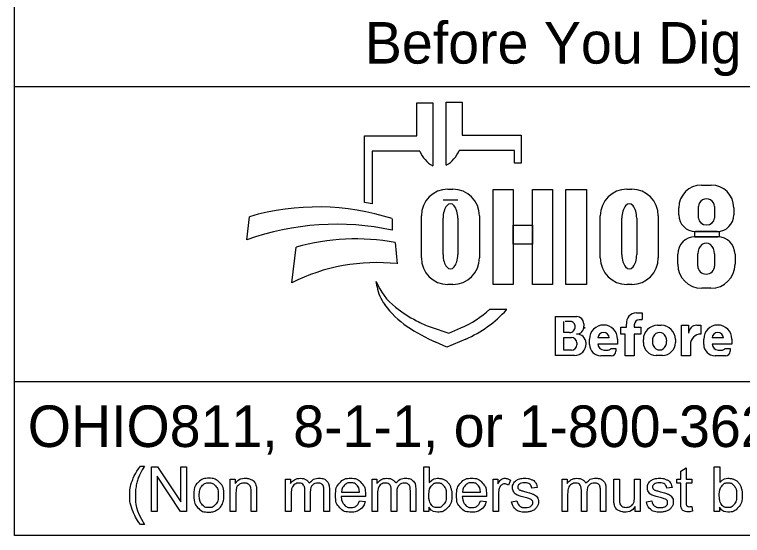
# Model space of a CAD drawing. Extents: x 0 to 34, y 0 to 22.
# Drawn here: x 2.978 to 5.431, y 2.143 to 3.897 of the extents above; entities that cross this region are included whole.
import ezdxf

# ---------------------------------------------------------------- set-up
doc = ezdxf.new("R2010")
doc.units = 0
doc.layers.add('SH_Data', color=7, linetype='Continuous')
doc.layers.add('SH_Text', color=7, linetype='Continuous')

msp = doc.modelspace()

# ---------------------------------------------------------------- linework, layer by layer
at = {"layer": 'SH_Data'}
for p, q in [((2.9775, 2.1428), (2.9775, 4.4803)), ((2.9775, 3.6553), (7.2275, 3.6553)), ((7.2275, 2.6607), (2.9775, 2.6607)), ((7.2275, 2.1428), (2.9775, 2.1428))]:
    msp.add_line(p, q, dxfattribs=at)
at = {"layer": 'SH_Text'}
for p, q in [((4.3335, 3.4883), (4.3335, 3.5998)), ((4.3335, 3.5998), (4.3872, 3.5998)), ((4.3872, 3.5998), (4.3872, 3.3877)), ((4.4329, 3.39), (4.4329, 3.6021)), ((4.4329, 3.6021), (4.4865, 3.6021)), ((4.4865, 3.6021), (4.4865, 3.4906)), ((4.1576, 3.2644), (4.1576, 3.4883)), ((4.1576, 3.4883), (4.3335, 3.4883)), ((4.4865, 3.4906), (4.6857, 3.4906)), ((4.6857, 3.4906), (4.6857, 3.3968)), ((4.1828, 3.4369), (4.1828, 3.26)), ((4.3439, 3.4369), (4.1828, 3.4369)), ((4.6625, 3.4392), (4.4761, 3.4392)), ((4.6625, 3.3968), (4.6625, 3.4392)), ((4.6857, 3.3968), (4.6625, 3.3968)), ((5.2931, 3.3231), (5.3258, 3.3231)), ((4.4385, 3.3091), (4.4551, 3.3091)), ((5.0416, 3.3091), (5.0581, 3.3091)), ((4.4718, 3.2721), (4.422, 3.2721)), ((5.2168, 3.2225), (5.2168, 3.2468)), ((5.283, 3.2111), (5.283, 3.2504)), ((5.3371, 3.2504), (5.3371, 3.2111)), ((5.4022, 3.2468), (5.4022, 3.2225)), ((3.7602, 3.1381), (3.7696, 3.2162)), ((4.3491, 3.0776), (4.3491, 3.2196)), ((4.5445, 3.2196), (4.5445, 3.0776)), ((4.9521, 3.0776), (4.9521, 3.2196)), ((5.1476, 3.2196), (5.1476, 3.0776)), ((4.2509, 3.2097), (4.2509, 3.1709)), ((4.422, 3.089), (4.422, 3.2114)), ((4.4718, 3.2114), (4.4718, 3.089)), ((5.025, 3.089), (5.025, 3.2114)), ((5.0748, 3.2114), (5.0748, 3.089)), ((5.3462, 3.1665), (5.2728, 3.1665)), ((5.271, 3.1482), (5.3483, 3.1482)), ((4.2608, 3.1291), (4.2671, 3.0582)), ((3.912, 2.9936), (3.9267, 3.1137)), ((5.2131, 3.0563), (5.2131, 3.0903)), ((5.2806, 3.0503), (5.2806, 3.0912)), ((5.3374, 3.0912), (5.3374, 3.0503)), ((5.4062, 3.0903), (5.4062, 3.0563)), ((4.1997, 2.9807), (4.1967, 2.9986)), ((4.4551, 2.9882), (4.4385, 2.9882)), ((5.0581, 2.9882), (5.0416, 2.9882)), ((5.3252, 2.9753), (5.2941, 2.9753)), ((4.58, 2.9048), (4.6375, 2.9048)), ((4.8013, 2.749), (4.8013, 2.8798)), ((4.8013, 2.8798), (4.8725, 2.8798)), ((5.0739, 2.8926), (5.0934, 2.8926)), ((5.0934, 2.8926), (5.0934, 2.8696)), ((4.8293, 2.8263), (4.8293, 2.8632)), ((4.8545, 2.8632), (4.8332, 2.8632)), ((4.8963, 2.856), (4.8963, 2.8481)), ((5.0406, 2.8442), (5.0406, 2.8546)), ((5.0667, 2.8526), (5.0667, 2.8442)), ((5.0934, 2.8691), (5.0832, 2.8691)), ((5.1451, 2.8508), (5.1573, 2.8508)), ((5.2254, 2.7478), (5.2254, 2.8505)), ((5.2254, 2.8505), (5.2499, 2.8505)), ((5.2499, 2.8505), (5.2499, 2.8237)), ((5.2772, 2.8505), (5.291, 2.8505)), ((5.291, 2.8505), (5.291, 2.8209)), ((4.3816, 2.8444), (4.441, 2.8239)), ((4.441, 2.8239), (4.4821, 2.8417)), ((4.8487, 2.8263), (4.8293, 2.8263)), ((5.0213, 2.8212), (5.0213, 2.8442)), ((5.0213, 2.8442), (5.0406, 2.8442)), ((5.0667, 2.8442), (5.0883, 2.8442)), ((5.0883, 2.8442), (5.0883, 2.8212)), ((4.4983, 2.8044), (4.435, 2.7769)), ((4.8293, 2.7669), (4.8293, 2.8097)), ((4.8293, 2.8097), (4.8548, 2.8097)), ((4.9159, 2.7858), (4.9159, 2.8042)), ((4.9824, 2.8082), (4.9439, 2.8082)), ((5.0104, 2.8042), (5.0104, 2.7866)), ((5.0362, 2.8212), (5.0213, 2.8212)), ((5.0362, 2.7478), (5.0362, 2.8212)), ((5.0883, 2.8212), (5.0667, 2.8212)), ((5.0667, 2.8212), (5.0667, 2.7478)), ((5.0973, 2.7922), (5.0973, 2.8029)), ((5.2051, 2.8029), (5.2051, 2.7922)), ((5.3008, 2.7858), (5.3008, 2.8042)), ((5.3674, 2.8082), (5.3288, 2.8082)), ((5.3953, 2.8042), (5.3953, 2.7866)), ((4.435, 2.7769), (4.3976, 2.7934)), ((4.8729, 2.7916), (4.8729, 2.7853)), ((4.9043, 2.7887), (4.9043, 2.7884)), ((5.0104, 2.7866), (4.944, 2.7866)), ((4.9876, 2.7729), (5.0045, 2.7729)), ((5.0045, 2.7729), (5.0045, 2.7631)), ((5.2559, 2.786), (5.2559, 2.7478)), ((5.3953, 2.7866), (5.3289, 2.7866)), ((5.3725, 2.7729), (5.3894, 2.7729)), ((5.3894, 2.7729), (5.3894, 2.7631)), ((4.865, 2.749), (4.8013, 2.749)), ((4.8546, 2.7669), (4.8293, 2.7669)), ((4.9649, 2.7673), (4.979, 2.7673)), ((5.1623, 2.7494), (5.1401, 2.7494)), ((5.3498, 2.7673), (5.3639, 2.7673)), ((4.9892, 2.7478), (4.9538, 2.7478)), ((5.0667, 2.7478), (5.0362, 2.7478)), ((5.2559, 2.7478), (5.2254, 2.7478)), ((5.3742, 2.7478), (5.3388, 2.7478))]:
    msp.add_line(p, q, dxfattribs=at)
for points in [[(4.591, 3.3081), (4.6589, 3.3081), (4.6589, 2.9881), (4.591, 2.9881)], [(4.7231, 3.3081), (4.7911, 3.3081), (4.7911, 2.9881), (4.7231, 2.9881)], [(4.8364, 3.3081), (4.9052, 3.3081), (4.9052, 2.9881), (4.8364, 2.9881)], [(4.6589, 3.1882), (4.7231, 3.1882), (4.7231, 3.1242), (4.6589, 3.1242)], [(5.2706, 3.1665), (5.3523, 3.1665), (5.3523, 3.1481), (5.2706, 3.1481)]]:
    msp.add_lwpolyline(points, close=True, dxfattribs=at)
for points in [[(3.4021, 2.3766), (3.4153, 2.3766)], [(3.4389, 2.2239), (3.4389, 2.3741), (3.4592, 2.3741), (3.5382, 2.2561), (3.5382, 2.3741), (3.5572, 2.3741), (3.5572, 2.2239), (3.5369, 2.2239), (3.4579, 2.3419), (3.4579, 2.2239), (3.4389, 2.2239)], [(4.3743, 2.2239), (4.3573, 2.2239), (4.3573, 2.3741), (4.3757, 2.3741), (4.3757, 2.3206)], [(5.2233, 2.2558), (5.2233, 2.3185), (5.2097, 2.3185), (5.2097, 2.3328), (5.2233, 2.3328), (5.2233, 2.3597), (5.2417, 2.3708), (5.2417, 2.3328), (5.2601, 2.3328), (5.2601, 2.3185), (5.2417, 2.3185), (5.2417, 2.2547)], [(5.3534, 2.2239), (5.3363, 2.2239), (5.3363, 2.3741), (5.3548, 2.3741), (5.3548, 2.3206)], [(3.7048, 2.2239), (3.7048, 2.3328), (3.7214, 2.3328), (3.7214, 2.3173)], [(3.8912, 2.2239), (3.8912, 2.3328), (3.9077, 2.3328), (3.9077, 2.3174)], [(4.1826, 2.2239), (4.1826, 2.3328), (4.1991, 2.3328), (4.1991, 2.3174)], [(4.5904, 2.2239), (4.5904, 2.3328), (4.607, 2.3328), (4.607, 2.3163)], [(4.8236, 2.2239), (4.8236, 2.3328), (4.8401, 2.3328), (4.8401, 2.3174)], [(4.9979, 2.2654), (4.9979, 2.3328), (5.0164, 2.3328), (5.0164, 2.2724)], [(5.0676, 2.2745), (5.0676, 2.3328), (5.0861, 2.3328), (5.0861, 2.2239), (5.0696, 2.2239)], [(4.6495, 2.3293), (4.643, 2.3122)], [(3.7233, 2.2833), (3.7233, 2.2239), (3.7048, 2.2239)], [(3.7932, 2.2908), (3.7932, 2.2239), (3.7748, 2.2239), (3.7748, 2.2901)], [(3.9743, 2.2871), (3.9743, 2.2239), (3.9559, 2.2239), (3.9559, 2.2946)], [(4.0388, 2.2986), (4.0388, 2.2239), (4.0203, 2.2239), (4.0203, 2.2924)], [(4.0799, 2.2887), (4.1406, 2.2887)], [(4.2657, 2.2871), (4.2657, 2.2239), (4.2473, 2.2239), (4.2473, 2.2946)], [(4.3301, 2.2986), (4.3301, 2.2239), (4.3117, 2.2239), (4.3117, 2.2924)], [(4.4879, 2.2887), (4.5486, 2.2887)], [(4.7394, 2.3046), (4.7213, 2.3022)], [(4.9067, 2.2871), (4.9067, 2.2239), (4.8883, 2.2239), (4.8883, 2.2946)], [(4.9711, 2.2986), (4.9711, 2.2239), (4.9527, 2.2239), (4.9527, 2.2924)], [(5.194, 2.3046), (5.1759, 2.3022)], [(3.9097, 2.2803), (3.9097, 2.2239), (3.8912, 2.2239)], [(4.16, 2.2736), (4.0788, 2.2736)], [(4.1404, 2.2591), (4.1595, 2.2567)], [(4.201, 2.2803), (4.201, 2.2239), (4.1826, 2.2239)], [(4.568, 2.2736), (4.4868, 2.2736)], [(4.5484, 2.2591), (4.5675, 2.2567)], [(4.6088, 2.2809), (4.6088, 2.2239), (4.5904, 2.2239)], [(4.653, 2.2564), (4.6712, 2.2593)], [(4.842, 2.2803), (4.842, 2.2239), (4.8236, 2.2239)], [(5.1076, 2.2564), (5.1258, 2.2593)], [(4.3743, 2.2375), (4.3743, 2.2239)], [(5.0696, 2.2239), (5.0696, 2.24)], [(5.2601, 2.2404), (5.2628, 2.2241)], [(5.3534, 2.2375), (5.3534, 2.2239)], [(3.4153, 2.1798), (3.4021, 2.1798)]]:
    msp.add_lwpolyline(points, dxfattribs=at)
for centre, radius, start, end in [((4.4353, 3.4736), 0.0985, 201.9296, 240.7469), ((4.3847, 3.476), 0.0985, 299.2531, 338.0704), ((5.2931, 3.2468), 0.0763, 90, 180), ((5.3258, 3.2468), 0.0763, 0, 90), ((4.4385, 3.2196), 0.0895, 90, 180), ((4.4551, 3.2196), 0.0895, 0, 90), ((5.0416, 3.2196), 0.0895, 90, 180), ((5.0581, 3.2196), 0.0895, 0, 90), ((4.0295, 2.4554), 0.8191, 79.2074, 81.0007), ((3.9997, 2.4302), 0.8191, 72.1402, 106.3144), ((5.2728, 3.2225), 0.056, 180, 270), ((5.3462, 3.2225), 0.056, 270, 0), ((4.0628, 2.2991), 0.8919, 77.8238, 109.8274), ((4.1267, 2.4094), 0.7322, 79.44, 105.8467), ((5.271, 3.0903), 0.0579, 90, 180), ((5.3483, 3.0903), 0.0579, 0, 90), ((4.4385, 3.0776), 0.0895, 180, 270), ((4.4551, 3.0776), 0.0895, 270, 0), ((5.0416, 3.0776), 0.0895, 180, 270), ((5.0581, 3.0776), 0.0895, 270, 0), ((4.1987, 2.4262), 0.6357, 83.8248, 116.8021), ((5.2941, 3.0563), 0.081, 180, 270), ((5.3252, 3.0563), 0.081, 270, 0), ((4.3841, 3.0707), 0.2008, 201.0457, 232.5314), ((4.341, 3.0048), 0.1433, 189.6817, 216.0884), ((4.4747, 3.1022), 0.3088, 216.0884, 235.7167), ((4.5766, 3.3219), 0.5173, 232.5314, 241.794), ((4.3387, 3.1722), 0.3602, 293.4582, 312.0712), ((4.3387, 3.1722), 0.401, 293.4582, 317.8286), ((4.8725, 2.856), 0.0238, 0, 90), ((5.0739, 2.859), 0.0335, 90, 187.5187), ((4.6412, 3.3465), 0.6044, 235.7167, 246.2325), ((4.4914, 3.1631), 0.3371, 241.794, 250.9821), ((4.8505, 2.8463), 0.0169, 357.8325, 90), ((4.8721, 2.8453), 0.0243, 270, 6.6529), ((4.9631, 2.8042), 0.0473, 0, 180), ((5.0832, 2.8526), 0.0165, 90, 180), ((5.1451, 2.8029), 0.0478, 90, 180), ((5.1573, 2.8029), 0.0478, 0, 90), ((5.2768, 2.8237), 0.0269, 89.2449, 180), ((5.3481, 2.8042), 0.0473, 0, 180), ((4.8487, 2.845), 0.0187, 270, 2.0582), ((4.8827, 2.8438), 0.0175, 347.4023, 0), ((4.9632, 2.8072), 0.0193, 2.9632, 177.0368), ((5.3481, 2.8072), 0.0193, 2.9632, 177.0368), ((4.8548, 2.7916), 0.0181, 0, 90), ((4.8722, 2.7889), 0.0321, 4.0748, 90), ((5.2908, 2.786), 0.0349, 89.6033, 180), ((4.8546, 2.7853), 0.0184, 270, 0), ((4.865, 2.7884), 0.0393, 270, 0), ((4.8714, 2.7887), 0.033, 0, 11.7502), ((4.9538, 2.7858), 0.038, 180, 270), ((4.9649, 2.7883), 0.021, 184.827, 270), ((4.979, 2.7767), 0.00938, 270, 335.9979), ((5.1401, 2.7922), 0.0428, 180, 270), ((5.1623, 2.7922), 0.0428, 270, 0), ((5.3388, 2.7858), 0.038, 180, 270), ((5.3498, 2.7883), 0.021, 184.827, 270), ((5.3639, 2.7767), 0.00938, 270, 335.9979), ((4.9892, 2.7631), 0.0152, 270, 0), ((5.3742, 2.7631), 0.0152, 270, 0)]:
    msp.add_arc(centre, radius, start, end, dxfattribs=at)
for centre, major_axis, ratio, start_param, end_param in [((5.31, 3.2504), (0.0271, 0), 0.969373, 0, 3.141593), ((4.4469, 3.2114), (0, 0.0484), 0.514403, 4.712389, 7.853982), ((5.0499, 3.2114), (0, 0.0484), 0.514403, 4.712389, 7.853982), ((5.31, 3.2111), (0.0271, 0), 0.818453, 3.141593, 6.283185), ((5.309, 3.0912), (0, 0.0358), 0.794529, 4.712389, 7.853982), ((4.4469, 3.089), (0, 0.0484), 0.514403, 1.570796, 4.712389), ((5.0499, 3.089), (0, 0.0484), 0.514403, 1.570796, 4.712389), ((5.309, 3.0503), (0.0284, 0), 0.959837, 3.141593, 6.283185), ((5.1517, 2.7976), (0, 0.029), 0.832186, 4.712389, 7.853982), ((5.1517, 2.7976), (0, 0.0302), 0.797287, 1.570796, 4.712389)]:
    msp.add_ellipse(centre, major_axis=major_axis, ratio=ratio, start_param=start_param, end_param=end_param, dxfattribs=at)
for points in [[(3.4021, 2.1798), (3.3869, 2.199), (3.3763, 2.2248), (3.3657, 2.2506), (3.3657, 2.2783), (3.3657, 2.3026), (3.3736, 2.325), (3.3829, 2.3509), (3.4021, 2.3766)], [(3.4153, 2.3766), (3.4029, 2.3553), (3.3989, 2.3462), (3.3927, 2.332), (3.3891, 2.3167), (3.3847, 2.2975), (3.3847, 2.2782), (3.3847, 2.2289), (3.4153, 2.1798)], [(3.5814, 2.2783), (3.5814, 2.3085), (3.5981, 2.3231), (3.6122, 2.3352), (3.6323, 2.3352), (3.6547, 2.3352), (3.669, 2.3205), (3.6832, 2.3058), (3.6832, 2.2799), (3.6832, 2.2589), (3.6769, 2.2469), (3.6706, 2.2348), (3.6586, 2.2282), (3.6466, 2.2215), (3.6323, 2.2215), (3.6095, 2.2215), (3.5954, 2.2362), (3.5814, 2.2508), (3.5814, 2.2783)], [(3.7214, 2.3173), (3.7334, 2.3352), (3.756, 2.3352), (3.7659, 2.3352), (3.7741, 2.3316), (3.7823, 2.3281), (3.7864, 2.3224), (3.7905, 2.3166), (3.7922, 2.3087), (3.7932, 2.3036), (3.7932, 2.2908)], [(3.9077, 2.3174), (3.9128, 2.3254), (3.9214, 2.3303), (3.9299, 2.3352), (3.9407, 2.3352), (3.9528, 2.3352), (3.9606, 2.3301), (3.9683, 2.3251), (3.9715, 2.3161), (3.9844, 2.3352), (4.0051, 2.3352), (4.0213, 2.3352), (4.03, 2.3262), (4.0388, 2.3172), (4.0388, 2.2986)], [(4.1595, 2.2567), (4.155, 2.24), (4.1428, 2.2307), (4.1306, 2.2215), (4.1117, 2.2215), (4.0878, 2.2215), (4.0738, 2.2362), (4.0598, 2.2509), (4.0598, 2.2774), (4.0598, 2.3049), (4.074, 2.32), (4.0881, 2.3352), (4.1106, 2.3352), (4.1324, 2.3352), (4.1463, 2.3203), (4.1601, 2.3055), (4.1601, 2.2785), (4.1601, 2.2769), (4.16, 2.2736)], [(4.1991, 2.3174), (4.2042, 2.3254), (4.2127, 2.3303), (4.2212, 2.3352), (4.2321, 2.3352), (4.2442, 2.3352), (4.2519, 2.3301), (4.2597, 2.3251), (4.2628, 2.3161), (4.2758, 2.3352), (4.2965, 2.3352), (4.3127, 2.3352), (4.3214, 2.3262), (4.3301, 2.3172), (4.3301, 2.2986)], [(4.3757, 2.3206), (4.3874, 2.3352), (4.4055, 2.3352), (4.4155, 2.3352), (4.4245, 2.3311), (4.4335, 2.3271), (4.4392, 2.3198), (4.445, 2.3124), (4.4483, 2.3021), (4.4516, 2.2918), (4.4516, 2.28), (4.4516, 2.252), (4.4378, 2.2368), (4.4239, 2.2215), (4.4046, 2.2215), (4.3853, 2.2215), (4.3743, 2.2375)], [(4.5675, 2.2567), (4.563, 2.24), (4.5508, 2.2307), (4.5386, 2.2215), (4.5196, 2.2215), (4.4958, 2.2215), (4.4818, 2.2362), (4.4678, 2.2509), (4.4678, 2.2774), (4.4678, 2.3049), (4.482, 2.32), (4.4961, 2.3352), (4.5186, 2.3352), (4.5404, 2.3352), (4.5543, 2.3203), (4.5681, 2.3055), (4.5681, 2.2785), (4.5681, 2.2769), (4.568, 2.2736)], [(4.607, 2.3163), (4.6133, 2.3278), (4.6187, 2.3315), (4.6241, 2.3352), (4.6305, 2.3352), (4.6398, 2.3352), (4.6495, 2.3293)], [(4.6712, 2.2593), (4.6727, 2.2483), (4.6798, 2.2425), (4.6868, 2.2366), (4.6995, 2.2366), (4.7122, 2.2366), (4.7184, 2.2418), (4.7245, 2.247), (4.7245, 2.254), (4.7245, 2.2602), (4.7191, 2.2638), (4.7153, 2.2663), (4.7002, 2.2701), (4.6799, 2.2752), (4.672, 2.2789), (4.6642, 2.2827), (4.6601, 2.2893), (4.6561, 2.2959), (4.6561, 2.3038), (4.6561, 2.3111), (4.6594, 2.3173), (4.6628, 2.3235), (4.6685, 2.3276), (4.6728, 2.3308), (4.6803, 2.333), (4.6877, 2.3352), (4.6962, 2.3352), (4.709, 2.3352), (4.7187, 2.3315), (4.7284, 2.3278), (4.733, 2.3215), (4.7377, 2.3152), (4.7394, 2.3046)], [(4.8401, 2.3174), (4.8452, 2.3254), (4.8537, 2.3303), (4.8622, 2.3352), (4.8731, 2.3352), (4.8852, 2.3352), (4.8929, 2.3301), (4.9007, 2.3251), (4.9038, 2.3161), (4.9168, 2.3352), (4.9375, 2.3352), (4.9537, 2.3352), (4.9624, 2.3262), (4.9711, 2.3172), (4.9711, 2.2986)], [(5.1258, 2.2593), (5.1273, 2.2483), (5.1343, 2.2425), (5.1414, 2.2366), (5.154, 2.2366), (5.1668, 2.2366), (5.1729, 2.2418), (5.1791, 2.247), (5.1791, 2.254), (5.1791, 2.2602), (5.1736, 2.2638), (5.1698, 2.2663), (5.1548, 2.2701), (5.1345, 2.2752), (5.1266, 2.2789), (5.1188, 2.2827), (5.1147, 2.2893), (5.1107, 2.2959), (5.1107, 2.3038), (5.1107, 2.3111), (5.114, 2.3173), (5.1173, 2.3235), (5.1231, 2.3276), (5.1274, 2.3308), (5.1348, 2.333), (5.1423, 2.3352), (5.1508, 2.3352), (5.1636, 2.3352), (5.1733, 2.3315), (5.183, 2.3278), (5.1876, 2.3215), (5.1922, 2.3152), (5.194, 2.3046)], [(5.3548, 2.3206), (5.3664, 2.3352), (5.3846, 2.3352), (5.3946, 2.3352), (5.4036, 2.3311), (5.4125, 2.3271), (5.4183, 2.3198), (5.4241, 2.3124), (5.4274, 2.3021), (5.4306, 2.2918), (5.4306, 2.28), (5.4306, 2.252), (5.4168, 2.2368), (5.403, 2.2215), (5.3836, 2.2215), (5.3644, 2.2215), (5.3534, 2.2375)], [(3.6003, 2.2783), (3.6003, 2.2574), (3.6094, 2.247), (3.6185, 2.2366), (3.6323, 2.2366), (3.646, 2.2366), (3.6551, 2.2471), (3.6642, 2.2575), (3.6642, 2.279), (3.6642, 2.2991), (3.6551, 2.3095), (3.6459, 2.3199), (3.6323, 2.3199), (3.6185, 2.3199), (3.6094, 2.3096), (3.6003, 2.2992), (3.6003, 2.2783)], [(3.7748, 2.2901), (3.7748, 2.3013), (3.7726, 2.3069), (3.7705, 2.3125), (3.765, 2.3158), (3.7595, 2.3191), (3.7521, 2.3191), (3.7404, 2.3191), (3.7318, 2.3117), (3.7233, 2.3042), (3.7233, 2.2833)], [(3.9559, 2.2946), (3.9559, 2.3069), (3.9514, 2.313), (3.9469, 2.3191), (3.9366, 2.3191), (3.9288, 2.3191), (3.9222, 2.315), (3.9156, 2.311), (3.9126, 2.3031), (3.9097, 2.2952), (3.9097, 2.2803)], [(4.0203, 2.2924), (4.0203, 2.3035), (4.0185, 2.3083), (4.0168, 2.3132), (4.012, 2.3162), (4.0073, 2.3191), (4.001, 2.3191), (3.9895, 2.3191), (3.9819, 2.3115), (3.9743, 2.3039), (3.9743, 2.2871)], [(4.1406, 2.2887), (4.1394, 2.3025), (4.1337, 2.3094), (4.1249, 2.3201), (4.1108, 2.3201), (4.0981, 2.3201), (4.0894, 2.3115), (4.0808, 2.303), (4.0799, 2.2887)], [(4.2473, 2.2946), (4.2473, 2.3069), (4.2428, 2.313), (4.2383, 2.3191), (4.228, 2.3191), (4.2202, 2.3191), (4.2136, 2.315), (4.207, 2.311), (4.204, 2.3031), (4.201, 2.2952), (4.201, 2.2803)], [(4.3117, 2.2924), (4.3117, 2.3035), (4.3099, 2.3083), (4.3081, 2.3132), (4.3034, 2.3162), (4.2987, 2.3191), (4.2923, 2.3191), (4.2809, 2.3191), (4.2733, 2.3115), (4.2657, 2.3039), (4.2657, 2.2871)], [(4.3741, 2.2792), (4.3741, 2.2596), (4.3794, 2.2509), (4.3881, 2.2366), (4.4029, 2.2366), (4.415, 2.2366), (4.4238, 2.2471), (4.4326, 2.2576), (4.4326, 2.2784), (4.4326, 2.2998), (4.4241, 2.3099), (4.4157, 2.3201), (4.4038, 2.3201), (4.3917, 2.3201), (4.3829, 2.3096), (4.3741, 2.299), (4.3741, 2.2792)], [(4.5486, 2.2887), (4.5474, 2.3025), (4.5417, 2.3094), (4.5328, 2.3201), (4.5188, 2.3201), (4.5061, 2.3201), (4.4974, 2.3115), (4.4888, 2.303), (4.4879, 2.2887)], [(4.643, 2.3122), (4.6363, 2.3162), (4.6295, 2.3162), (4.6235, 2.3162), (4.6187, 2.3125), (4.6139, 2.3089), (4.6119, 2.3024), (4.6088, 2.2926), (4.6088, 2.2809)], [(4.7213, 2.3022), (4.7201, 2.3106), (4.7142, 2.3153), (4.7083, 2.3201), (4.6975, 2.3201), (4.6848, 2.3201), (4.6794, 2.3159), (4.6739, 2.3116), (4.6739, 2.306), (4.6739, 2.3024), (4.6762, 2.2995), (4.6785, 2.2966), (4.6833, 2.2946), (4.686, 2.2936), (4.6996, 2.2899), (4.7192, 2.2847), (4.7269, 2.2813), (4.7347, 2.278), (4.7391, 2.2717), (4.7435, 2.2653), (4.7435, 2.2559), (4.7435, 2.2467), (4.7381, 2.2386), (4.7327, 2.2304), (4.7226, 2.226), (4.7124, 2.2215), (4.6996, 2.2215), (4.6784, 2.2215), (4.6672, 2.2303), (4.6561, 2.2391), (4.653, 2.2564)], [(4.8883, 2.2946), (4.8883, 2.3069), (4.8838, 2.313), (4.8793, 2.3191), (4.869, 2.3191), (4.8612, 2.3191), (4.8546, 2.315), (4.848, 2.311), (4.845, 2.3031), (4.842, 2.2952), (4.842, 2.2803)], [(4.9527, 2.2924), (4.9527, 2.3035), (4.9509, 2.3083), (4.9491, 2.3132), (4.9444, 2.3162), (4.9397, 2.3191), (4.9333, 2.3191), (4.9219, 2.3191), (4.9143, 2.3115), (4.9067, 2.3039), (4.9067, 2.2871)], [(5.1759, 2.3022), (5.1747, 2.3106), (5.1688, 2.3153), (5.1629, 2.3201), (5.1521, 2.3201), (5.1394, 2.3201), (5.1339, 2.3159), (5.1285, 2.3116), (5.1285, 2.306), (5.1285, 2.3024), (5.1308, 2.2995), (5.133, 2.2966), (5.1378, 2.2946), (5.1406, 2.2936), (5.1542, 2.2899), (5.1737, 2.2847), (5.1815, 2.2813), (5.1893, 2.278), (5.1937, 2.2717), (5.1981, 2.2653), (5.1981, 2.2559), (5.1981, 2.2467), (5.1927, 2.2386), (5.1873, 2.2304), (5.1772, 2.226), (5.167, 2.2215), (5.1542, 2.2215), (5.1329, 2.2215), (5.1218, 2.2303), (5.1107, 2.2391), (5.1076, 2.2564)], [(5.3532, 2.2792), (5.3532, 2.2596), (5.3585, 2.2509), (5.3672, 2.2366), (5.382, 2.2366), (5.3941, 2.2366), (5.4029, 2.2471), (5.4116, 2.2576), (5.4116, 2.2784), (5.4116, 2.2998), (5.4032, 2.3099), (5.3948, 2.3201), (5.3828, 2.3201), (5.3708, 2.3201), (5.362, 2.3096), (5.3532, 2.299), (5.3532, 2.2792)], [(4.0788, 2.2736), (4.0799, 2.2557), (4.089, 2.2462), (4.0981, 2.2366), (4.1117, 2.2366), (4.1219, 2.2366), (4.1291, 2.242), (4.1362, 2.2473), (4.1404, 2.2591)], [(4.4868, 2.2736), (4.4879, 2.2557), (4.497, 2.2462), (4.5061, 2.2366), (4.5197, 2.2366), (4.5299, 2.2366), (4.537, 2.242), (4.5442, 2.2473), (4.5484, 2.2591)], [(5.0696, 2.24), (5.0569, 2.2215), (5.0351, 2.2215), (5.0255, 2.2215), (5.0171, 2.2252), (5.0088, 2.2289), (5.0047, 2.2345), (5.0007, 2.2401), (4.9991, 2.2482), (4.9979, 2.2536), (4.9979, 2.2654)], [(5.0164, 2.2724), (5.0164, 2.258), (5.0175, 2.253), (5.0192, 2.2457), (5.0249, 2.2416), (5.0305, 2.2374), (5.0388, 2.2374), (5.0471, 2.2374), (5.0543, 2.2417), (5.0616, 2.2459), (5.0646, 2.2533), (5.0676, 2.2606), (5.0676, 2.2745)], [(5.2628, 2.2241), (5.255, 2.2224), (5.2488, 2.2224), (5.2388, 2.2224), (5.2333, 2.2256), (5.2278, 2.2288), (5.2255, 2.234), (5.2233, 2.2392), (5.2233, 2.2558)], [(5.2417, 2.2547), (5.2417, 2.2468), (5.2427, 2.2445), (5.2436, 2.2423), (5.2458, 2.2409), (5.248, 2.2396), (5.2521, 2.2396), (5.2551, 2.2396), (5.2601, 2.2404)]]:
    msp.add_open_spline(points, degree=3, dxfattribs=at)

# ---------------------------------------------------------------- texts
for s, p in [('Before You Dig', (4.1583, 3.7321)), ('OHIO811, 8-1-1, or 1-800-362-2764', (3.022, 2.4406))]:
    msp.add_text(s, height=0.14, dxfattribs=at).set_placement(p)

doc.saveas('drawing.dxf')
